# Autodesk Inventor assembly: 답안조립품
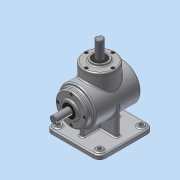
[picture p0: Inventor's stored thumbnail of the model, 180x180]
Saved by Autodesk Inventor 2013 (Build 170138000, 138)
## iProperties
Created: 2015-07
Part Number: 답안조립품
Document SubType Name: Assembly
Designer: dgall
Author: dgall
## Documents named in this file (14)
- C:\Users\dgall\Desktop\450705V1002\답안조립품.iam
- C:\Users\dgall\Desktop\450705V1002\본체.ipt
- C:\Users\dgall\Desktop\450705V1002\메인 축.ipt
- 메인 축.ipt
- C:\Users\dgall\Desktop\450705V1002\서브 축.ipt
- 서브 축.ipt
- C:\Users\dgall\Desktop\450705V1002\커버.ipt
- C:\Users\dgall\Desktop\450705V1002\M4.ipt
- C:\Users\dgall\Desktop\450705V1002\메인 베벨기어.ipt
- C:\Users\dgall\Desktop\450705V1002\서브 베벨기어.ipt
- C:\Users\dgall\Desktop\450705V1002\키 4x4.ipt
- C:\Users\dgall\Desktop\450705V1002\키 5x5.ipt
- C:\Users\dgall\Desktop\450705V1002\베어링 6203.ipt
- C:\Users\dgall\Desktop\450705V1002\오일실.ipt
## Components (8 placed, 1 different names)
1. M4:1
2. M4:6
3. M4:7
4. M4:8
5. M4:5
6. M4:9
7. M4:10
8. M4:11
